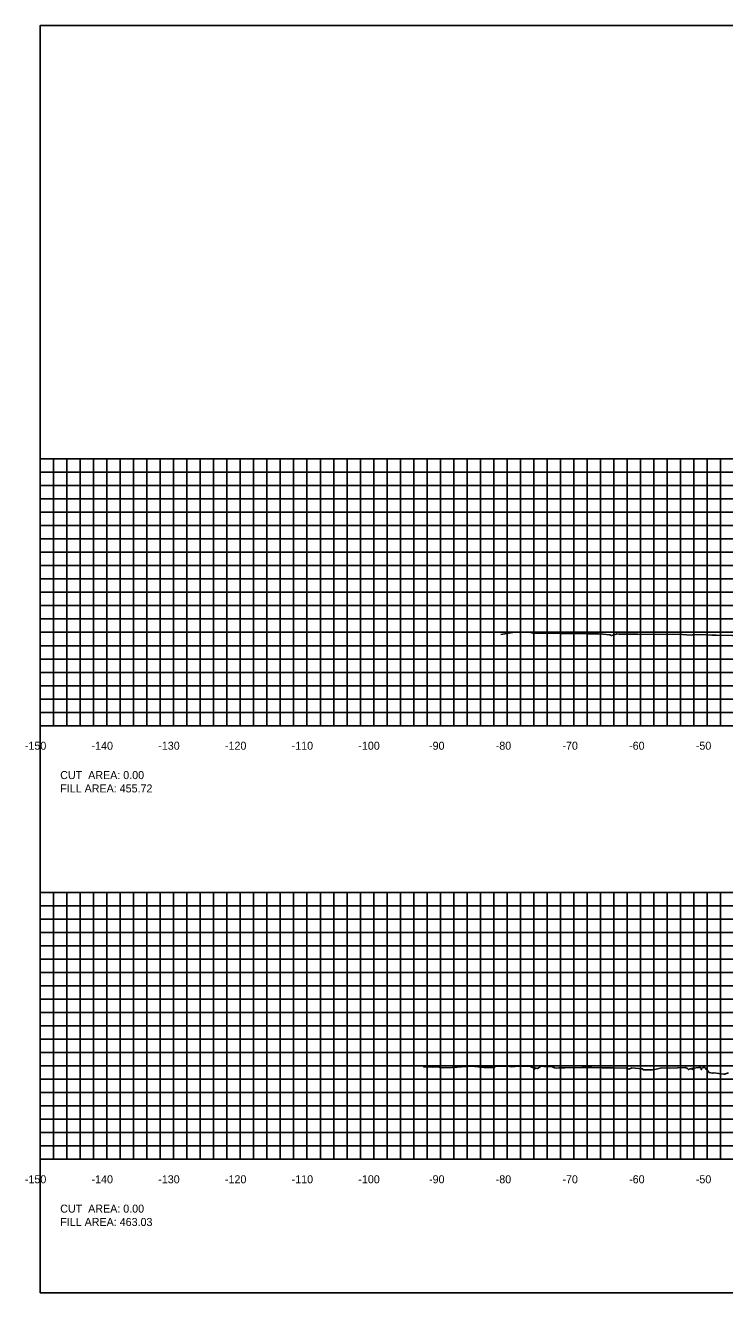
# Model space of a CAD drawing. Extents: x 1797518 to 1804843, y 248068 to 251132.
# Drawn here: x 1802818.8 to 1802923.6, y 250079.4 to 250269.4 of the extents above; entities that cross this region are included whole.
import ezdxf

# ---------------------------------------------------------------- set-up
doc = ezdxf.new("R2010")
doc.units = 0
for name, color, linetype in [('10', 7, 'Continuous'), ('60', 7, 'Continuous'), ('ANNO-TXT', 7, 'Continuous'), ('Level 62', 7, 'Continuous'), ('M-ROADS', 7, 'Continuous')]:
    doc.layers.add(name, color=color, linetype=linetype)

msp = doc.modelspace()

# ---------------------------------------------------------------- linework, layer by layer
msp.add_lwpolyline([(1802821, 250079.43), (1803121, 250079.43), (1803121, 250269.43), (1802821, 250269.43)], close=True)
at = {"layer": '60'}
for p, q in [((1802820.94, 250204.43), (1802821, 250204.43)), ((1802821, 250164.43), (1802821, 250204.43)), ((1802820.94, 250194.43), (1802821, 250194.43)), ((1802820.94, 250184.43), (1802821, 250184.43)), ((1802820.94, 250174.43), (1802821, 250174.43)), ((1802820.94, 250164.43), (1802821, 250164.43)), ((1802821, 250164.43), (1803121, 250164.43)), ((1802821, 250164.37), (1802821, 250164.43)), ((1802831, 250164.37), (1802831, 250164.43)), ((1802841, 250164.37), (1802841, 250164.43)), ((1802851, 250164.37), (1802851, 250164.43)), ((1802861, 250164.37), (1802861, 250164.43)), ((1802871, 250164.37), (1802871, 250164.43)), ((1802881, 250164.37), (1802881, 250164.43)), ((1802891, 250164.37), (1802891, 250164.43)), ((1802901, 250164.37), (1802901, 250164.43)), ((1802911, 250164.37), (1802911, 250164.43)), ((1802921, 250164.37), (1802921, 250164.43)), ((1802820.94, 250139.43), (1802821, 250139.43)), ((1802821, 250099.43), (1802821, 250139.43)), ((1802820.94, 250129.43), (1802821, 250129.43)), ((1802820.94, 250119.43), (1802821, 250119.43)), ((1802820.94, 250109.43), (1802821, 250109.43)), ((1802820.94, 250099.43), (1802821, 250099.43)), ((1802821, 250099.43), (1803121, 250099.43)), ((1802821, 250099.37), (1802821, 250099.43)), ((1802831, 250099.37), (1802831, 250099.43)), ((1802841, 250099.37), (1802841, 250099.43)), ((1802851, 250099.37), (1802851, 250099.43)), ((1802861, 250099.37), (1802861, 250099.43)), ((1802871, 250099.37), (1802871, 250099.43)), ((1802881, 250099.37), (1802881, 250099.43)), ((1802891, 250099.37), (1802891, 250099.43)), ((1802901, 250099.37), (1802901, 250099.43)), ((1802911, 250099.37), (1802911, 250099.43)), ((1802921, 250099.37), (1802921, 250099.43))]:
    msp.add_line(p, q, dxfattribs=at)
at = {"layer": 'Level 62'}
for p, q in [((1802821, 250204.43), (1803121, 250204.43)), ((1802821, 250164.43), (1802821, 250204.43)), ((1802823, 250164.43), (1802823, 250204.43)), ((1802825, 250164.43), (1802825, 250204.43)), ((1802827, 250164.43), (1802827, 250204.43)), ((1802829, 250164.43), (1802829, 250204.43)), ((1802831, 250164.43), (1802831, 250204.43)), ((1802833, 250164.43), (1802833, 250204.43)), ((1802835, 250164.43), (1802835, 250204.43)), ((1802837, 250164.43), (1802837, 250204.43)), ((1802839, 250164.43), (1802839, 250204.43)), ((1802841, 250164.43), (1802841, 250204.43)), ((1802843, 250164.43), (1802843, 250204.43)), ((1802845, 250164.43), (1802845, 250204.43)), ((1802847, 250164.43), (1802847, 250204.43)), ((1802849, 250164.43), (1802849, 250204.43)), ((1802851, 250164.43), (1802851, 250204.43)), ((1802853, 250164.43), (1802853, 250204.43)), ((1802855, 250164.43), (1802855, 250204.43)), ((1802857, 250164.43), (1802857, 250204.43)), ((1802859, 250164.43), (1802859, 250204.43)), ((1802861, 250164.43), (1802861, 250204.43)), ((1802863, 250164.43), (1802863, 250204.43)), ((1802865, 250164.43), (1802865, 250204.43)), ((1802867, 250164.43), (1802867, 250204.43)), ((1802869, 250164.43), (1802869, 250204.43)), ((1802871, 250164.43), (1802871, 250204.43)), ((1802873, 250164.43), (1802873, 250204.43)), ((1802875, 250164.43), (1802875, 250204.43)), ((1802877, 250164.43), (1802877, 250204.43)), ((1802879, 250164.43), (1802879, 250204.43)), ((1802881, 250164.43), (1802881, 250204.43)), ((1802883, 250164.43), (1802883, 250204.43)), ((1802885, 250164.43), (1802885, 250204.43)), ((1802887, 250164.43), (1802887, 250204.43)), ((1802889, 250164.43), (1802889, 250204.43)), ((1802891, 250164.43), (1802891, 250204.43)), ((1802893, 250164.43), (1802893, 250204.43)), ((1802895, 250164.43), (1802895, 250204.43)), ((1802897, 250164.43), (1802897, 250204.43)), ((1802899, 250164.43), (1802899, 250204.43)), ((1802901, 250164.43), (1802901, 250204.43)), ((1802903, 250164.43), (1802903, 250204.43)), ((1802905, 250164.43), (1802905, 250204.43)), ((1802907, 250164.43), (1802907, 250204.43)), ((1802909, 250164.43), (1802909, 250204.43)), ((1802911, 250164.43), (1802911, 250204.43)), ((1802913, 250164.43), (1802913, 250204.43)), ((1802915, 250164.43), (1802915, 250204.43)), ((1802917, 250164.43), (1802917, 250204.43)), ((1802919, 250164.43), (1802919, 250204.43)), ((1802921, 250164.43), (1802921, 250204.43)), ((1802923, 250164.43), (1802923, 250204.43)), ((1802821, 250202.43), (1803121, 250202.43)), ((1802821, 250200.43), (1803121, 250200.43)), ((1802821, 250198.43), (1803121, 250198.43)), ((1802821, 250196.43), (1803121, 250196.43)), ((1802821, 250194.43), (1803121, 250194.43)), ((1802821, 250192.43), (1803121, 250192.43)), ((1802821, 250190.43), (1803121, 250190.43)), ((1802821, 250188.43), (1803121, 250188.43)), ((1802821, 250186.43), (1803121, 250186.43)), ((1802821, 250184.43), (1803121, 250184.43)), ((1802821, 250182.43), (1803121, 250182.43)), ((1802821, 250180.43), (1803121, 250180.43)), ((1802821, 250178.43), (1803121, 250178.43)), ((1802821, 250176.43), (1803121, 250176.43)), ((1802821, 250174.43), (1803121, 250174.43)), ((1802821, 250172.43), (1803121, 250172.43)), ((1802821, 250170.43), (1803121, 250170.43)), ((1802821, 250168.43), (1803121, 250168.43)), ((1802821, 250166.43), (1803121, 250166.43)), ((1802821, 250164.43), (1803121, 250164.43)), ((1802821, 250139.43), (1803121, 250139.43)), ((1802821, 250099.43), (1802821, 250139.43)), ((1802823, 250099.43), (1802823, 250139.43)), ((1802825, 250099.43), (1802825, 250139.43)), ((1802827, 250099.43), (1802827, 250139.43)), ((1802829, 250099.43), (1802829, 250139.43)), ((1802831, 250099.43), (1802831, 250139.43)), ((1802833, 250099.43), (1802833, 250139.43)), ((1802835, 250099.43), (1802835, 250139.43)), ((1802837, 250099.43), (1802837, 250139.43)), ((1802839, 250099.43), (1802839, 250139.43)), ((1802841, 250099.43), (1802841, 250139.43)), ((1802843, 250099.43), (1802843, 250139.43)), ((1802845, 250099.43), (1802845, 250139.43)), ((1802847, 250099.43), (1802847, 250139.43)), ((1802849, 250099.43), (1802849, 250139.43)), ((1802851, 250099.43), (1802851, 250139.43)), ((1802853, 250099.43), (1802853, 250139.43)), ((1802855, 250099.43), (1802855, 250139.43)), ((1802857, 250099.43), (1802857, 250139.43)), ((1802859, 250099.43), (1802859, 250139.43)), ((1802861, 250099.43), (1802861, 250139.43)), ((1802863, 250099.43), (1802863, 250139.43)), ((1802865, 250099.43), (1802865, 250139.43)), ((1802867, 250099.43), (1802867, 250139.43)), ((1802869, 250099.43), (1802869, 250139.43)), ((1802871, 250099.43), (1802871, 250139.43)), ((1802873, 250099.43), (1802873, 250139.43)), ((1802875, 250099.43), (1802875, 250139.43)), ((1802877, 250099.43), (1802877, 250139.43)), ((1802879, 250099.43), (1802879, 250139.43)), ((1802881, 250099.43), (1802881, 250139.43)), ((1802883, 250099.43), (1802883, 250139.43)), ((1802885, 250099.43), (1802885, 250139.43)), ((1802887, 250099.43), (1802887, 250139.43)), ((1802889, 250099.43), (1802889, 250139.43)), ((1802891, 250099.43), (1802891, 250139.43)), ((1802893, 250099.43), (1802893, 250139.43)), ((1802895, 250099.43), (1802895, 250139.43)), ((1802897, 250099.43), (1802897, 250139.43)), ((1802899, 250099.43), (1802899, 250139.43)), ((1802901, 250099.43), (1802901, 250139.43)), ((1802903, 250099.43), (1802903, 250139.43)), ((1802905, 250099.43), (1802905, 250139.43)), ((1802907, 250099.43), (1802907, 250139.43)), ((1802909, 250099.43), (1802909, 250139.43)), ((1802911, 250099.43), (1802911, 250139.43)), ((1802913, 250099.43), (1802913, 250139.43)), ((1802915, 250099.43), (1802915, 250139.43)), ((1802917, 250099.43), (1802917, 250139.43)), ((1802919, 250099.43), (1802919, 250139.43)), ((1802921, 250099.43), (1802921, 250139.43)), ((1802923, 250099.43), (1802923, 250139.43)), ((1802821, 250137.43), (1803121, 250137.43)), ((1802821, 250135.43), (1803121, 250135.43)), ((1802821, 250133.43), (1803121, 250133.43)), ((1802821, 250131.43), (1803121, 250131.43)), ((1802821, 250129.43), (1803121, 250129.43)), ((1802821, 250127.43), (1803121, 250127.43)), ((1802821, 250125.43), (1803121, 250125.43)), ((1802821, 250123.43), (1803121, 250123.43)), ((1802821, 250121.43), (1803121, 250121.43)), ((1802821, 250119.43), (1803121, 250119.43)), ((1802821, 250117.43), (1803121, 250117.43)), ((1802821, 250115.43), (1803121, 250115.43)), ((1802821, 250113.43), (1803121, 250113.43)), ((1802821, 250111.43), (1803121, 250111.43)), ((1802821, 250109.43), (1803121, 250109.43)), ((1802821, 250107.43), (1803121, 250107.43)), ((1802821, 250105.43), (1803121, 250105.43)), ((1802821, 250103.43), (1803121, 250103.43)), ((1802821, 250101.43), (1803121, 250101.43)), ((1802821, 250099.43), (1803121, 250099.43))]:
    msp.add_line(p, q, dxfattribs=at)
at = {"layer": 'M-ROADS'}
for points in [[(1802890.07, 250178.13), (1802891.53, 250178.35), (1802891.87, 250178.42), (1802892.32, 250178.43), (1802894.55, 250178.38), (1802894.92, 250178.32), (1802902.93, 250178.22), (1802904.69, 250178.19), (1802905.34, 250178.18), (1802906.41, 250178.06), (1802906.67, 250177.95), (1802907.37, 250178.18), (1802907.48, 250178.2), (1802907.77, 250178.18), (1802910.01, 250178.18), (1802910.45, 250178.18), (1802910.59, 250178.18), (1802917.28, 250178.11), (1802918.62, 250178.02), (1802918.85, 250178.08), (1802919.53, 250178.09), (1802921.06, 250178.08), (1802921.69, 250178.01), (1802922.1, 250178), (1802922.37, 250178.01), (1802927.23, 250177.91)], [(1802878.49, 250113.25), (1802879.53, 250113.27), (1802879.77, 250113.25), (1802880.52, 250113.3), (1802881.44, 250113.12), (1802882.84, 250113.19), (1802885.59, 250113.38), (1802886.71, 250113.31), (1802887.54, 250113.19), (1802889.09, 250113.19), (1802889.32, 250113.41), (1802890.99, 250113.41), (1802891.72, 250113.31), (1802892.7, 250113.4), (1802893.9, 250113.4), (1802894.52, 250113.34), (1802895.08, 250113.11), (1802895.08, 250112.88), (1802895.21, 250113.14), (1802895.36, 250113.09), (1802895.56, 250113.03), (1802896.11, 250113.4), (1802896.92, 250113.3), (1802897.69, 250113.32), (1802898.13, 250113.14), (1802898.47, 250113.09), (1802898.79, 250113.15), (1802899.66, 250113.16), (1802902.28, 250113.17), (1802903.69, 250113.17), (1802905.24, 250113.16), (1802906.79, 250113.15), (1802908.93, 250113.09), (1802909.24, 250112.93), (1802909.6, 250113.1), (1802909.69, 250113.15), (1802911.23, 250113.01), (1802911.44, 250112.86), (1802911.62, 250112.85), (1802911.84, 250112.84), (1802912.8, 250112.85), (1802913.37, 250112.96), (1802914.13, 250113.13), (1802915.38, 250113.08), (1802917.7, 250113.17), (1802918.07, 250113.04), (1802918.2, 250112.87), (1802918.45, 250113.01), (1802918.63, 250113.05), (1802918.77, 250112.87), (1802918.85, 250113.07), (1802918.9, 250113.08), (1802919.74, 250113.19), (1802919.76, 250113.19), (1802920.05, 250113.2), (1802920.09, 250113.16), (1802920.12, 250112.85), (1802920.17, 250113.01), (1802920.36, 250113.17), (1802920.47, 250113.17), (1802920.63, 250113.17), (1802921.28, 250112.42), (1802921.81, 250112.33), (1802921.99, 250112.4), (1802923.52, 250112.17), (1802923.59, 250112.17), (1802923.61, 250112.17), (1802924.18, 250112.39)]]:
    msp.add_lwpolyline(points, dxfattribs=at)

# ---------------------------------------------------------------- texts
at = {"layer": '10'}
for s, p in [('-150', (1802818.7, 250160.83)), ('-140', (1802828.7, 250160.83)), ('-130', (1802838.7, 250160.83)), ('-120', (1802848.7, 250160.83)), ('-110', (1802858.7, 250160.83)), ('-100', (1802868.7, 250160.83)), ('-90', (1802879.3, 250160.83)), ('-80', (1802889.3, 250160.83)), ('-70', (1802899.3, 250160.83)), ('-60', (1802909.3, 250160.83)), ('-50', (1802919.3, 250160.83)), ('-150', (1802818.7, 250095.83)), ('-140', (1802828.7, 250095.83)), ('-130', (1802838.7, 250095.83)), ('-120', (1802848.7, 250095.83)), ('-110', (1802858.7, 250095.83)), ('-100', (1802868.7, 250095.83)), ('-90', (1802879.3, 250095.83)), ('-80', (1802889.3, 250095.83)), ('-70', (1802899.3, 250095.83)), ('-60', (1802909.3, 250095.83)), ('-50', (1802919.3, 250095.83))]:
    msp.add_text(s, height=1.2, dxfattribs=at).set_placement(p)
at = {"layer": '60'}
for p in [(1802821, 250164.43), (1802821, 250099.43)]:
    msp.add_text('-', height=0.0001, dxfattribs=at).set_placement(p)
at = {"layer": 'ANNO-TXT'}
for s, p in [('CUT  AREA: 0.00', (1802824, 250156.43)), ('FILL AREA: 455.72', (1802824, 250154.43)), ('CUT  AREA: 0.00', (1802824, 250091.43)), ('FILL AREA: 463.03', (1802824, 250089.43))]:
    msp.add_text(s, height=1.2, dxfattribs=at).set_placement(p)

doc.saveas('drawing.dxf')
